// Mitsubishi GX Works2 project: ChangeMapping_Q   PLC: Q03UDV

TYPE SERVO_OBJECT : STRUCT
  wIndex : INT;  (* Index *)
  wSubIndex : INT;  (* Subindex *)
  dData : DINT;  (* Data *)
  wSize : INT;  (* Object size *)
END_STRUCT END_TYPE

TYPE EXTERNAL_DEVICE : STRUCT
  wIPaddress : ARRAY [0..1] OF INT;  (* IP address of external device *)
  wPortNo : INT;  (* Destination port number *)
  wResendNum : INT;  (* Number of resends *)
  wMonitoringTime : INT;  (* Arrival monitoring time *)
END_STRUCT END_TYPE

FUNCTION_BLOCK SVFB_WriteObject  // [00A] Object writing
VAR_INPUT
  i_bEN : BOOL;  (* Execution command *)
  i_stExtDevice : EXTERNAL_DEVICE;  (* External device *)
  i_stObjectInfo : SERVO_OBJECT;  (* Object information *)
END_VAR
VAR_OUTPUT
  o_bOK : BOOL;  (* Normal completion *)
  o_bErr : BOOL;  (* Error completion *)
  o_uErrID : WORD;  (* Error code *)
END_VAR
VAR
  w20CtrlData : ARRAY [0..19] OF INT;  (* SLMP Control data *)
  w10ReqData : ARRAY [0..9] OF INT;  (* SLMP Request frame *)
  w10ResData : ARRAY [0..9] OF INT;  (* SLMP Response frame *)
  b2ExecFlag : ARRAY [0..1] OF BOOL;  (* SLMP Completion device *)
END_VAR
VAR_OUTPUT
  o_bENO : BOOL;  (* Execution status *)
END_VAR
VAR
  wIPaddr12 : INT;  (* IP address *)
  wIPaddr34 : INT;  (* IP address *)
  wPortNo : INT;  (* Port number *)
  sDummy : STRING[32];  (* Dummy *)
  bBusy : BOOL;  (* Executing *)
  wResend : INT;  (* Number of resends *)
  wMonTime : INT;  (* Arrival monitoring time *)
  wIndex : INT;  (* Object index *)
  wSubIndex : INT;  (* Object sub index *)
  wSize : INT;  (* Object data size *)
  udData : DWORD;  (* Object data *)
  wDataL : INT;  (* data *)
  wDataH : INT;  (* data *)
  bInitialize : BOOL;  (* Initialization flag *)
END_VAR
(**************************************************************************
*
*    <FB NAME>    	SVFB_WriteObject
*    <Description>  	サーボアンプのオブジェクトデータを指定値に変更します。
*							Change the object data of the servo amplifier to the specified value.
*
*    COPYRIGHT (C) 2016 MITSUBISHI ELECTRIC CORPORATION ALL RIGHT RESERVED
**************************************************************************)

IF i_bEN THEN
	IF NOT(bInitialize) THEN
		bInitialize := TRUE;
		o_bENO	:= TRUE;
		o_uErrID	:= 0;

		(*--------------------------------------------------------------*
		|	入力ラベル取込み / Input label acquisition
		*---------------------------------------------------------------*)
		wIPaddr12	:= i_stExtDevice.wIPaddress[0];
		wIPaddr34	:= i_stExtDevice.wIPaddress[1];
		wPortNo		:= i_stExtDevice.wPortNo;
		wResend 	:= i_stExtDevice.wResendNum;
		wMonTime	:= i_stExtDevice.wMonitoringTime;
		wIndex		:= i_stObjectInfo.wIndex;
		wSubIndex	:= i_stObjectInfo.wSubIndex;
		wSize			:= i_stObjectInfo.wSize;
		udData		:= DINT_TO_DWORD(i_stObjectInfo.dData);
		wDataL		:= DWORD_TO_INT(udData);
		wDataH		:= DWORD_TO_INT(SHR(udData, 16));

		(* 入力ラベル範囲チェック / Input label range check *)
		MOV(((wResend < 0) OR (wResend > 15)), 3, wResend);
		MOV((wMonTime < 0), 0, wMonTime);
		MOV(((wSize < 1) OR (wSize > 4)), H100, o_uErrID);			(* エラーコード出力 / Error code output *)

		(*--------------------------------------------------------------*
		|	コントロールデータ / Control data
		*---------------------------------------------------------------*)
(*		FMOV(TRUE, K0, K20, w20CtrlData[0]);	*)		(* クリア / Clear *)
		w20CtrlData[0]  := H8081;				(* 実行・異常時完了タイプ / Execution/error completion type *)
		w20CtrlData[1]  := H0000;				(* 完了ステータス / Completion status *)
		w20CtrlData[2]  := H0002;				(* 自局使用チャンネル / Own station channel *)
		w20CtrlData[3]  := wIPaddr34;		(* 相手機器IPアドレス(第3，4オクテット) / IP address of external device (third and fourth octets) *)
		w20CtrlData[4]  := wIPaddr12;		(* 相手機器IPアドレス(第1，2オクテット) / IP address of external device (first and second octets) *)
		w20CtrlData[5]  := wPortNo;			(* 相手機器ポート番号 / Destination port number *)
		w20CtrlData[6]  := H0000;				(* 要求先ネットワーク番号 / Request destination network number *)
		w20CtrlData[7]  := H00FF;				(* 要求先局番 / Request destination station number *)
		w20CtrlData[8]  := H03FF;				(* 要求先ユニットI/O番号 / Request destination module I/O number *)
		w20CtrlData[9]  := H0000;				(* 要求先マルチドロップ局番 / Request destination multidrop station number *)
		w20CtrlData[10] := wResend;			(* 再送回数 / Number of resends *)
		w20CtrlData[11] := wMonTime;		(* 到達監視時間 / Arrival monitoring time *)
		w20CtrlData[12] := H0000;				(* 時計セットフラグ / Clock setting flag *)
		w20CtrlData[13] := H0000;				(* 時計データ(月・年下2桁)  / Clock data(Month, Year) *)
		w20CtrlData[14] := H0000;				(* 時計データ(時・日) / Clock data(Hour, Day) *)
		w20CtrlData[15] := H0000;				(* 時計データ(秒・分) / Clock data(Second, Minute) *)
		w20CtrlData[16] := H0000;				(* 時計データ(年上2桁・曜日)/ Clock data(Year, Day of the week) *)
		w20CtrlData[17] := H0000;				(* 異常検出機器IPアドレス(第3，4オクテット) / IP address of error detected device *)
		w20CtrlData[18] := H0000;				(* 異常検出機器IPアドレス(第1，2オクテット) / IP address of error detected device *)

		(*--------------------------------------------------------------*
		|	要求フレーム / Request frame
		*---------------------------------------------------------------*)
(*		FMOV(TRUE, K0, K10, w10ReqData[0]);	*)		(* クリア / Clear *)
		w10ReqData[0] := 12 + wSize;							(* 要求データ長 / Request data length *)
		w10ReqData[1] := K10;									(* 監視タイマ / Monitoring timer *)
		w10ReqData[2] := H4020;								(* コマンド / Command *)
		w10ReqData[3] := H2;									(* サブコマンド / Sub command *)
		w10ReqData[4] := wIndex;								(* インデックス / Index *)
		w10ReqData[5] := wSubIndex;							(* サブインデックス / Sub index *)
		w10ReqData[6] := wSize;								(* データサイズ / Number of data value *)
		w10ReqData[7] := wDataL;								(* データ(L) / Data(L) *)
		w10ReqData[8] := wDataH;								(* データ(H) / Data(H) *)

		(*--------------------------------------------------------------*
		|	応答フレーム / Response frame
		*---------------------------------------------------------------*)
		FMOV(TRUE, K0, K10, w10ResData[0]);			(* クリア / Clear *)

		(*--------------------------------------------------------------*
		|	命令完了の状態 / Completion status
		*---------------------------------------------------------------*)
		b2ExecFlag[0] := FALSE;				(* 完了デバイス / Completion device *)
		b2ExecFlag[1] := FALSE;				(* 完了時の状態表示デバイス / Completion status indication device *)

		IF (o_uErrID = 0) THEN
			bBusy := TRUE;
		ELSE
			o_bErr := TRUE;						(* エラー出力 / Error output *)
		END_IF;
	END_IF;

	(*--------------------------------------------------------------*
	|	要求送信 / Send request frame
	*---------------------------------------------------------------*)
	SP_SLMPSND(bBusy, sDummy, w20CtrlData[0], w10ReqData[0], w10ResData[0], b2ExecFlag);

	(*--------------------------------------------------------------*
	|	応答待ち / Waiting to receive response frame
	*---------------------------------------------------------------*)
	IF (bBusy) THEN
		IF b2ExecFlag[0] THEN			(* 命令完了 / Command Completion *)
			IF b2ExecFlag[1] THEN		(* 異常完了 / Abnormal completion *)
				o_bErr	:= TRUE;			(* エラー出力 / Error output *)
				o_uErrID	:= H200;			(* エラーコード出力 / Error code output *)
			ELSE
				IF (w10ResData[1] = 0) THEN
					o_bOK := TRUE;		(* 正常完了 / Normal completion *)
				ELSE
					o_bErr	:= TRUE;		(* エラー出力 / Error output *)
					o_uErrID	:= H200;		(* エラーコード出力 / Error code output *)
				END_IF;
			END_IF;
			bBusy := FALSE;
		END_IF;
	END_IF;

ELSE
	bInitialize	:= FALSE;
	bBusy		:= FALSE;
	o_bENO		:= FALSE;
	o_bOK		:= FALSE;
	o_bErr		:= FALSE;
	o_uErrID		:= 0;
END_IF;
END_FUNCTION_BLOCK

PROGRAM ServoObjectRW
VAR
  ExecuteRead : BOOL;  (* Execution command *)
  ExtDevice : EXTERNAL_DEVICE;  (* External device *)
  ObjectInfo : SERVO_OBJECT;  (* Object information *)
  ReadErrorID : WORD;  (* Error code *)
  WriteErrorID : WORD;  (* Error code *)
  ReadOK : BOOL;  (* Normal completion *)
  ReadError : BOOL;  (* Error completion *)
  WriteOK : BOOL;  (* Normal completion *)
  WriteError : BOOL;  (* Error completion *)
  SVFB_WriteObject_1 : SVFB_WriteObject;  (* Function block *)
  SVFB_ReadObject_1 : SVFB_ReadObject;  (* Function block *)
  ReadData : DINT;  (* Read data *)
  ExecuteWrite : BOOL;  (* Execution command *)
END_VAR
(* structured ladder/FBD written out as ST: instructions are called as NAME(EN, inputs, outputs); _pN, _eN, _tN stand for wires *)
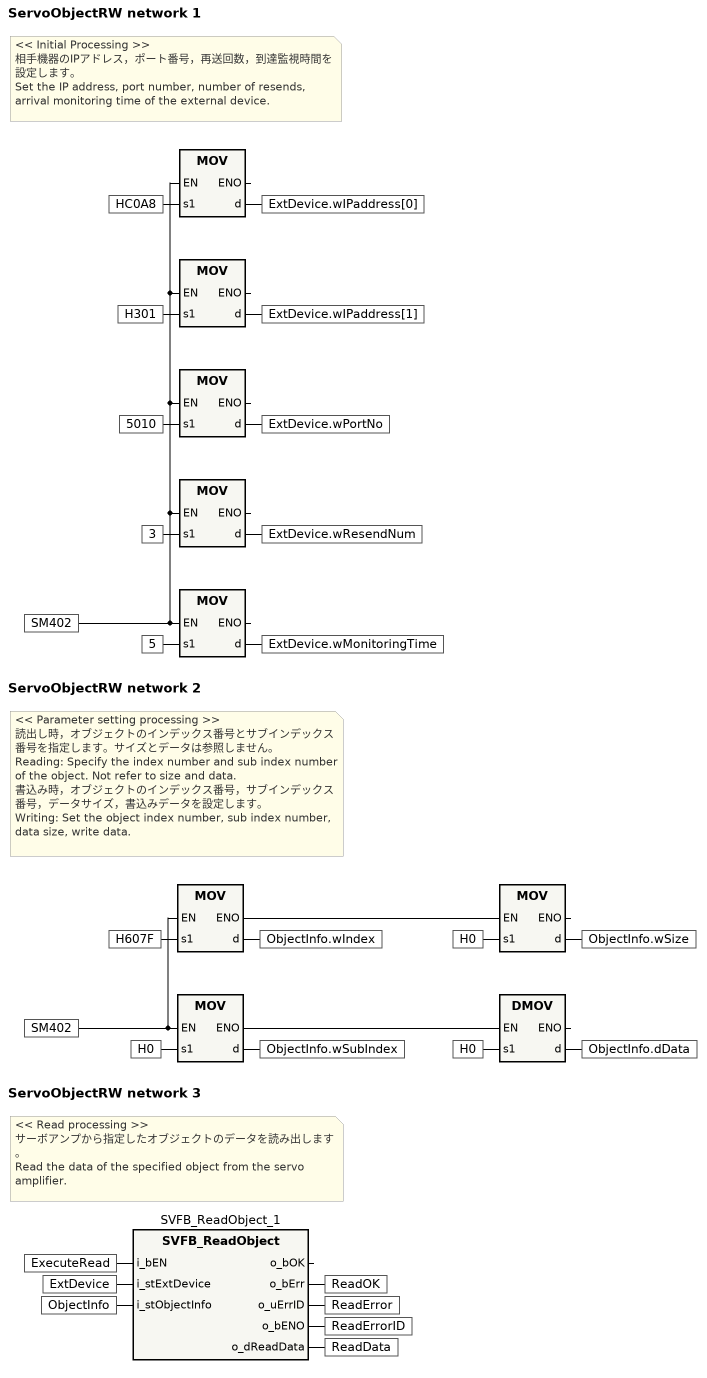
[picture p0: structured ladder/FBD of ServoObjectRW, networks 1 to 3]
(* network 1 *)
(* << Initial Processing >> /  / 相手機器のIPアドレス，ポート番号，再送回数，到達監視時間を設定します。 / Set the IP address, port number, number of resends, arrival monitoring time of the external device. *)
MOV(SM402, HC0A8, ExtDevice.wIPaddress[0]);
MOV(SM402, H301, ExtDevice.wIPaddress[1]);
MOV(SM402, 5010, ExtDevice.wPortNo);
MOV(SM402, 3, ExtDevice.wResendNum);
MOV(SM402, 5, ExtDevice.wMonitoringTime);
(* network 2 *)
(* << Parameter setting processing >> /  / 読出し時，オブジェクトのインデックス番号とサブインデックス番号を指定します。サイズとデータは参照しません。 / Reading: Specify the index number and sub index number of the object. Not refer to size and data. /  / 書込み時，オブジェクトのインデックス番号，サブインデックス番号，データサイズ，書込みデータを設定します。 / Writing: Set the object index number, sub index number, data size, write data. *)
_e1 := MOV(SM402, H607F, ObjectInfo.wIndex);
MOV(_e1, H0, ObjectInfo.wSize);
_e2 := MOV(SM402, H0, ObjectInfo.wSubIndex);
DMOV(_e2, H0, ObjectInfo.dData);
(* network 3 *)
(* << Read processing >> /  / サーボアンプから指定したオブジェクトのデータを読み出します。 / Read the data of the specified object from the servo amplifier. *)
SVFB_ReadObject_1(i_bEN := ExecuteRead, i_stExtDevice := ExtDevice, i_stObjectInfo := ObjectInfo, o_bErr => ReadOK, o_uErrID => ReadError, o_bENO => ReadErrorID, o_dReadData => ReadData);
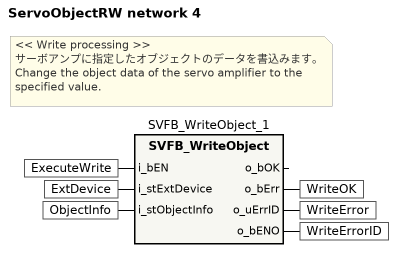
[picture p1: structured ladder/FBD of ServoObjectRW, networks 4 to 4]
(* network 4 *)
(* << Write processing >> /  / サーボアンプに指定したオブジェクトのデータを書込みます。 / Change the object data of the servo amplifier to the specified value. *)
SVFB_WriteObject_1(i_bEN := ExecuteWrite, i_stExtDevice := ExtDevice, i_stObjectInfo := ObjectInfo, o_bErr => WriteOK, o_uErrID => WriteError, o_bENO => WriteErrorID);
END_PROGRAM

FUNCTION_BLOCK SVFB_ReadObject  // [00A] Object reading
VAR_INPUT
  i_bEN : BOOL;  (* Execution command *)
  i_stExtDevice : EXTERNAL_DEVICE;  (* External device *)
  i_stObjectInfo : SERVO_OBJECT;  (* Object information *)
END_VAR
VAR_OUTPUT
  o_bOK : BOOL;  (* Normal completion *)
  o_bErr : BOOL;  (* Error completion *)
  o_uErrID : WORD;  (* Error code *)
END_VAR
VAR
  w20CtrlData : ARRAY [0..19] OF INT;  (* SLMP Control data *)
  w10ReqData : ARRAY [0..9] OF INT;  (* SLMP Request frame *)
  w10ResData : ARRAY [0..9] OF INT;  (* SLMP Response frame *)
  b2ExecFlag : ARRAY [0..1] OF BOOL;  (* SLMP Completion device *)
END_VAR
VAR_OUTPUT
  o_bENO : BOOL;  (* Execution status *)
END_VAR
VAR
  wIndex : INT;  (* Object index *)
  wSubIndex : INT;  (* Object sub index *)
  sDummy : STRING[32];  (* Dummy *)
  wReadData : INT;  (* Read data *)
  dReadData : DINT;  (* Read data *)
END_VAR
VAR_OUTPUT
  o_dReadData : DINT;  (* Read data *)
END_VAR
VAR
  udReadData : DWORD;  (* Read data *)
  bBusy : BOOL;  (* Executing *)
  wIPaddr12 : INT;  (* IP address *)
  wIPaddr34 : INT;  (* IP address *)
  wPortNo : INT;  (* Port number *)
  wResend : INT;  (* Number of resends *)
  wMonTime : INT;  (* Arrival monitoring time *)
  bInitialize : BOOL;  (* Initialization flag *)
END_VAR
(**************************************************************************
*
*    <FB NAME>		SVFB_ReadObject
*    <Description>		サーボアンプから指定オブジェクトのデータを読み出します。
*							Read the data of the specified object from the servo amplifier.
*
*    COPYRIGHT (C) 2016 MITSUBISHI ELECTRIC CORPORATION ALL RIGHT RESERVED
**************************************************************************)

IF i_bEN THEN
	IF NOT(bInitialize) THEN
		bInitialize	:= TRUE;
		o_bENO	:= TRUE;
		o_uErrID	:= 0;
		o_dReadData := 0;
		dReadData := 0;

		(*--------------------------------------------------------------*
		|	入力ラベル取込み / Input label acquisition
		*---------------------------------------------------------------*)
		wIPaddr12	:= i_stExtDevice.wIPaddress[0];
		wIPaddr34	:= i_stExtDevice.wIPaddress[1];
		wPortNo		:= i_stExtDevice.wPortNo;
		wResend 	:= i_stExtDevice.wResendNum;
		wMonTime	:= i_stExtDevice.wMonitoringTime;
		wIndex		:= i_stObjectInfo.wIndex;
		wSubIndex	:= i_stObjectInfo.wSubIndex;

		(* 入力ラベル範囲チェック / Input label range check *)
		MOV(((wResend < 0) OR (wResend > 15)), 3, wResend);
		MOV((wMonTime < 0), 0, wMonTime);

		(*--------------------------------------------------------------*
		|	コントロールデータ / Control data
		*---------------------------------------------------------------*)
(*		FMOV(TRUE, K0, K20, w20CtrlData[0]);	*)		(* クリア / Clear *)
		w20CtrlData[0]  := H8081;				(* 実行・異常時完了タイプ / Execution/error completion type *)
		w20CtrlData[1]  := H0000;				(* 完了ステータス / Completion status *)
		w20CtrlData[2]  := H0002;				(* 自局使用チャンネル / Own station channel *)
		w20CtrlData[3]  := wIPaddr34;		(* 相手機器IPアドレス(第3，4オクテット) / IP address of external device (third and fourth octets) *)
		w20CtrlData[4]  := wIPaddr12;		(* 相手機器IPアドレス(第1，2オクテット) / IP address of external device (first and second octets) *)
		w20CtrlData[5]  := wPortNo;			(* 相手機器ポート番号 / Destination port number *)
		w20CtrlData[6]  := H0000;				(* 要求先ネットワーク番号 / Request destination network number *)
		w20CtrlData[7]  := H00FF;				(* 要求先局番 / Request destination station number *)
		w20CtrlData[8]  := H03FF;				(* 要求先ユニットI/O番号 / Request destination module I/O number *)
		w20CtrlData[9]  := H0000;				(* 要求先マルチドロップ局番 / Request destination multidrop station number *)
		w20CtrlData[10] := wResend;			(* 再送回数 / Number of resends *)
		w20CtrlData[11] := wMonTime;		(* 到達監視時間 / Arrival monitoring time *)
		w20CtrlData[12] := H0000;				(* 時計セットフラグ / Clock setting flag *)
		w20CtrlData[13] := H0000;				(* 時計データ(月・年下2桁)  / Clock data(Month, Year) *)
		w20CtrlData[14] := H0000;				(* 時計データ(時・日) / Clock data(Hour, Day) *)
		w20CtrlData[15] := H0000;				(* 時計データ(秒・分) / Clock data(Second, Minute) *)
		w20CtrlData[16] := H0000;				(* 時計データ(年上2桁・曜日)/ Clock data(Year, Day of the week) *)
		w20CtrlData[17] := H0000;				(* 異常検出機器IPアドレス(第3，4オクテット) / IP address of error detected device *)
		w20CtrlData[18] := H0000;				(* 異常検出機器IPアドレス(第1，2オクテット) / IP address of error detected device *)

		(*--------------------------------------------------------------*
		|	要求フレーム / Request frame
		*---------------------------------------------------------------*)
(*		FMOV(TRUE, K0, K10, w10ReqData[0]);	*)		(* クリア / Clear *)
		w10ReqData[0] := 12;									(* 要求データ長 / Request data length *)
		w10ReqData[1] := K10;									(* 監視タイマ / Monitoring timer *)
		w10ReqData[2] := H4020;								(* コマンド / Command *)
		w10ReqData[3] := H1;									(* サブコマンド / Sub command *)
		w10ReqData[4] := wIndex;								(* インデックス / Index *)
		w10ReqData[5] := wSubIndex;							(* サブインデックス / Sub index *)
		w10ReqData[6] := 0;										(* データサイズ / Number of data value *)

		(*--------------------------------------------------------------*
		|	応答フレーム / Response frame
		*---------------------------------------------------------------*)
		FMOV(TRUE, K0, K10, w10ResData[0]);			(* クリア / Clear *)

		(*--------------------------------------------------------------*
		|	命令完了の状態 / Completion status
		*---------------------------------------------------------------*)
		b2ExecFlag[0] := FALSE;				(* 完了デバイス / Completion device *)
		b2ExecFlag[1] := FALSE;				(* 完了時の状態表示デバイス / Completion status indication device *)

		bBusy := TRUE;
	END_IF;

	(*--------------------------------------------------------------*
	|	要求送信 / Send request frame
	*---------------------------------------------------------------*)
	SP_SLMPSND(bBusy, sDummy, w20CtrlData[0], w10ReqData[0], w10ResData[0], b2ExecFlag);

	(*--------------------------------------------------------------*
	|	応答待ち / Waiting to receive response frame
	*---------------------------------------------------------------*)
	IF (bBusy) THEN
		IF b2ExecFlag[0] THEN			(* 命令完了 / Command Completion *)
			IF b2ExecFlag[1] THEN		(* 異常完了 / Abnormal completion *)
				o_bErr	:= TRUE;			(* エラー出力 / Error output *)
				o_uErrID	:= H200;			(* エラーコード出力 / Error code output *)
			ELSE								(* 正常完了 / Normal completion *)
				IF (w10ResData[1] = 0) THEN
					IF (w10ResData[4] <= 2) THEN
						MOV(TRUE, w10ResData[5], wReadData);
						dReadData := INT_TO_DINT(wReadData);
					ELSE
						udReadData := SHL(INT_TO_DWORD(w10ResData[6]), 16);
						udReadData := udReadData OR (INT_TO_DWORD(w10ResData[5]));
						dReadData := DWORD_TO_DINT(udReadData);
					END_IF;
					o_bOK := TRUE;
					o_dReadData := dReadData;
				ELSE
					o_bErr	:= TRUE;		(* エラー出力 / Error output *)
					o_uErrID	:= H200;		(* エラーコード出力 / Error code output *)
				END_IF;
			END_IF;
			bBusy := FALSE;
		END_IF;
	END_IF;

ELSE
	bInitialize	:= FALSE;
	bBusy		:= FALSE;
	o_bENO		:= FALSE;
	o_bOK		:= FALSE;
	o_bErr		:= FALSE;
	o_uErrID		:= 0;
END_IF;
END_FUNCTION_BLOCK

FUNCTION_BLOCK SVFB_WriteMultiObject  // [00A] Writing multiple objects
VAR_INPUT
  i_stExtDevice : EXTERNAL_DEVICE;  (* External device *)
  i_stObjectTbl : ARRAY [0..33] OF SERVO_OBJECT;  (* Object table *)
  i_wNum : INT;  (* Number registered *)
  i_bEN : BOOL;  (* Execution command *)
END_VAR
VAR_OUTPUT
  o_bENO : BOOL;  (* Execution status *)
  o_bOK : BOOL;  (* Normal completion *)
  o_bBusy : BOOL;  (* Executing *)
  o_bErr : BOOL;  (* Error completion *)
  o_uErrID : WORD;  (* Error code *)
END_VAR
VAR
  bFbEn : BOOL;  (* FB execution command *)
  bFbEno : BOOL;  (* FB execution status *)
  bFbOk : BOOL;  (* FB normal completion *)
  bFbErr : BOOL;  (* FB error completion *)
  uFbErrID : WORD;  (* FB error code *)
  wInstructSQ : INT;  (* Sequence number *)
  wNum : INT;  (* Number registered *)
  SVFB_WriteObject_1 : SVFB_WriteObject;  (* Function block *)
  wWaitCount : INT;
  bInitialize : BOOL;  (* Initialization flag *)
  wIndex : INT;  (* Index *)
END_VAR
(**************************************************************************
*
*    <FB NAME>    	SVFB_WriteMultiObject
*    <Description>  	サーボアンプの複数のオブジェクトデータを変更します。
*							Changes multiple object data of the servo amplifier.
*
*    COPYRIGHT (C) 2016 MITSUBISHI ELECTRIC CORPORATION ALL RIGHT RESERVED
**************************************************************************)

IF i_bEN THEN
	IF NOT(bInitialize) THEN
		bInitialize := TRUE;
		o_bENO	:= TRUE;
		o_uErrID	:= 0;

		wIndex	:= 0;
		wWaitCount := 0;

		(* 入力ラベル範囲チェック / Input label range check *)
		wNum := i_wNum;
		IF ((wNum < 1) OR (wNum > 34)) THEN
			o_uErrID := H101;
			wInstructSQ := 3;
		ELSE
			o_bBusy := TRUE;
			bFbEn	:= TRUE;
			wInstructSQ := 1;
		END_IF;
	END_IF;

	(*--------------------------------------------------------------*
	|	オブジェクトデータ書込み / Writing object data
	*---------------------------------------------------------------*)
	SVFB_WriteObject_1(i_bEN := bFbEn, i_stExtDevice := i_stExtDevice, i_stObjectInfo := i_stObjectTbl[wIndex],
								o_bENO := bFbEno, o_bOK := bFbOk, o_bErr := bFbErr, o_uErrID := uFbErrID);

	IF (wInstructSQ = 1) THEN		(* ファンクションブロック完了待ち / Wait for completion of function block *)
		IF bFbOk THEN
			wInstructSQ := 2;
		ELSIF bFbErr THEN
			o_uErrID := uFbErrID;
			wInstructSQ := 2;
		ELSE
			;
		END_IF;
	ELSIF (wInstructSQ = 2) THEN	(* 命令リセットと次データセット / Instruction reset and next data set *)
		IF bFbEn THEN
			bFbEn := FALSE;
		ELSE
			IF (o_uErrID = 0) THEN
				wWaitCount := wWaitCount + 1;
				IF (wWaitCount > 2) THEN
					wWaitCount := 0;
					wIndex := wIndex + 1;
					IF (wIndex >= wNum) THEN
						wInstructSQ := 3;
					ELSE
						bFbEn	:= TRUE;
						wInstructSQ := 1;
					END_IF;
				END_IF;
			ELSE
				wInstructSQ := 3;
			END_IF;
		END_IF;
	ELSE										(* 終了処理 / End processing *)
		IF (o_uErrID = 0) THEN
			o_bOK	:= TRUE;
			o_bErr	:= FALSE;
		ELSE
			o_bOK	:= FALSE;
			o_bErr	:= TRUE;
		END_IF;
		o_bBusy	:= FALSE;
	END_IF;

ELSE
	bInitialize := FALSE;
	wInstructSQ := 0;
	wIndex	:= 0;
	bFbEn	:= FALSE;
	bFbEno	:= FALSE;
	bFbOk	:= FALSE;
	bFbErr	:= FALSE;
	uFbErrID := 0;

	o_bENO	:= FALSE;
	o_bOK	:= FALSE;
	o_bBusy	:= FALSE;
	o_bErr	:= FALSE;
	o_uErrID	:= 0;
END_IF;
END_FUNCTION_BLOCK

PROGRAM ChangeMap
VAR
  AmpInfo : EXTERNAL_DEVICE;  (* External device *)
  MapTable : ARRAY [0..33] OF SERVO_OBJECT;  (* Object information *)
  StartChangeMap : BOOL;  (* Execution command *)
  Done : BOOL;  (* Normal completion *)
  Error : BOOL;  (* Error completion *)
  ErrorID : WORD;  (* Error code *)
  SVFB_WriteMultiObject_1 : SVFB_WriteMultiObject;  (* Function block *)
END_VAR
(* structured ladder/FBD written out as ST: instructions are called as NAME(EN, inputs, outputs); _pN, _eN, _tN stand for wires *)
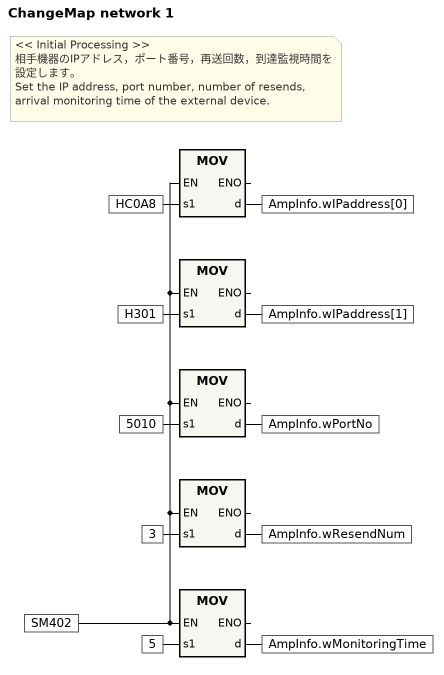
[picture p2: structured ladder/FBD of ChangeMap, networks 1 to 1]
(* network 1 *)
(* << Initial Processing >> /  / 相手機器のIPアドレス，ポート番号，再送回数，到達監視時間を設定します。 / Set the IP address, port number, number of resends, arrival monitoring time of the external device. *)
MOV(SM402, HC0A8, AmpInfo.wIPaddress[0]);
MOV(SM402, H301, AmpInfo.wIPaddress[1]);
MOV(SM402, 5010, AmpInfo.wPortNo);
MOV(SM402, 3, AmpInfo.wResendNum);
MOV(SM402, 5, AmpInfo.wMonitoringTime);
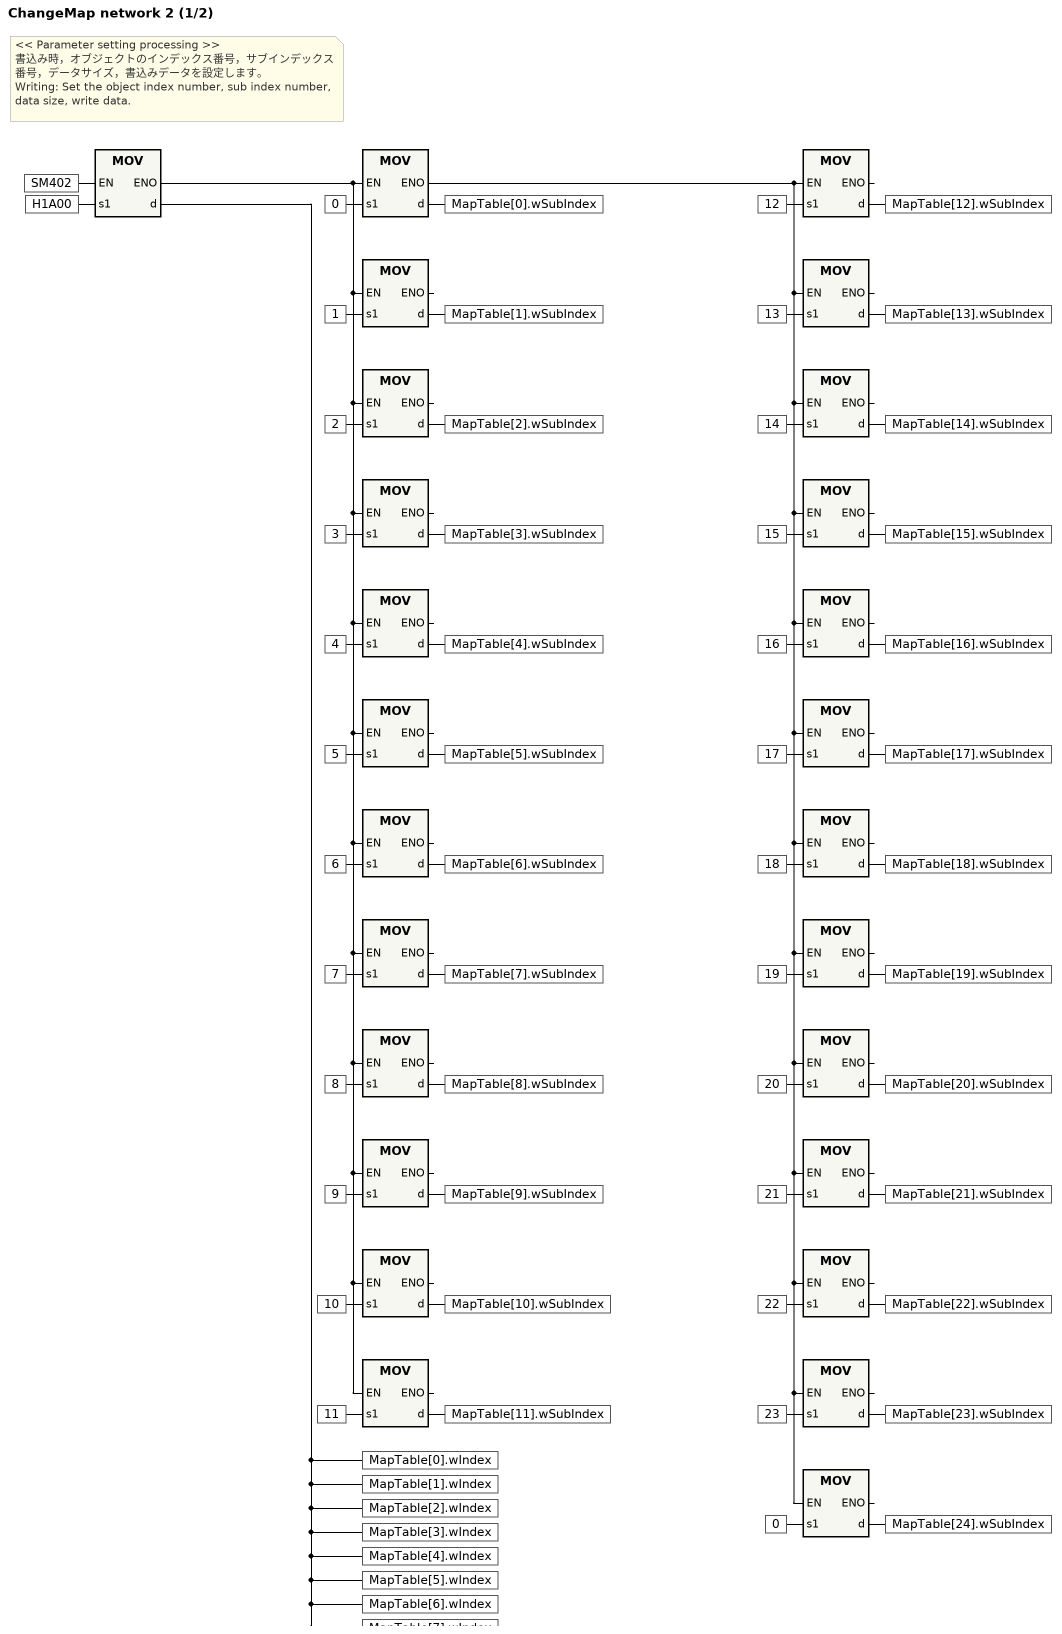
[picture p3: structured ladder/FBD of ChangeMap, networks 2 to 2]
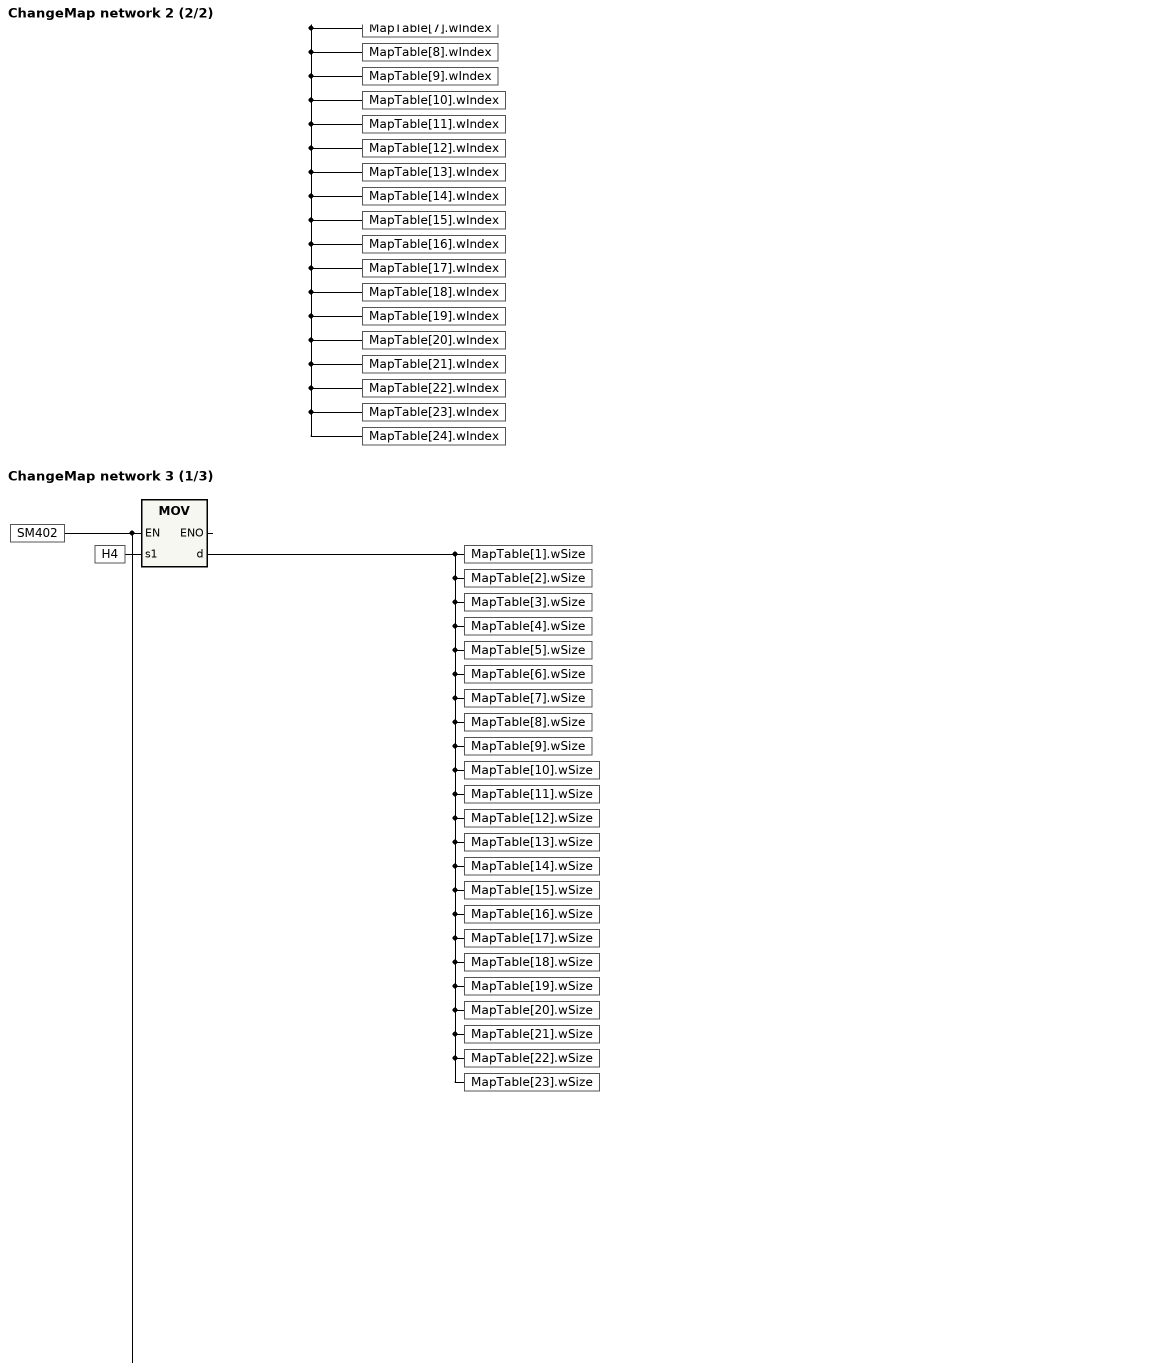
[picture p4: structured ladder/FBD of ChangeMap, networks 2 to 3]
(* network 2 *)
(* << Parameter setting processing >> /  / 書込み時，オブジェクトのインデックス番号，サブインデックス番号，データサイズ，書込みデータを設定します。 / Writing: Set the object index number, sub index number, data size, write data. *)
_e1 := MOV(SM402, H1A00, MapTable[0].wIndex);
_e2 := MOV(_e1, 0, MapTable[0].wSubIndex);
MOV(_e2, 12, MapTable[12].wSubIndex);
MapTable[1].wIndex := MapTable[0].wIndex;
MapTable[2].wIndex := MapTable[0].wIndex;
MapTable[3].wIndex := MapTable[0].wIndex;
MOV(_e1, 1, MapTable[1].wSubIndex);
MOV(_e2, 13, MapTable[13].wSubIndex);
MapTable[4].wIndex := MapTable[0].wIndex;
MapTable[5].wIndex := MapTable[0].wIndex;
MapTable[6].wIndex := MapTable[0].wIndex;
MapTable[7].wIndex := MapTable[0].wIndex;
MOV(_e1, 2, MapTable[2].wSubIndex);
MOV(_e2, 14, MapTable[14].wSubIndex);
MapTable[8].wIndex := MapTable[0].wIndex;
MapTable[9].wIndex := MapTable[0].wIndex;
MapTable[10].wIndex := MapTable[0].wIndex;
MapTable[11].wIndex := MapTable[0].wIndex;
MOV(_e1, 3, MapTable[3].wSubIndex);
MOV(_e2, 15, MapTable[15].wSubIndex);
MapTable[12].wIndex := MapTable[0].wIndex;
MapTable[13].wIndex := MapTable[0].wIndex;
MapTable[14].wIndex := MapTable[0].wIndex;
MapTable[15].wIndex := MapTable[0].wIndex;
MOV(_e1, 4, MapTable[4].wSubIndex);
MOV(_e2, 16, MapTable[16].wSubIndex);
MapTable[16].wIndex := MapTable[0].wIndex;
MapTable[17].wIndex := MapTable[0].wIndex;
MapTable[18].wIndex := MapTable[0].wIndex;
MapTable[19].wIndex := MapTable[0].wIndex;
MOV(_e1, 5, MapTable[5].wSubIndex);
MOV(_e2, 17, MapTable[17].wSubIndex);
MapTable[20].wIndex := MapTable[0].wIndex;
MapTable[21].wIndex := MapTable[0].wIndex;
MapTable[22].wIndex := MapTable[0].wIndex;
MapTable[23].wIndex := MapTable[0].wIndex;
MOV(_e1, 6, MapTable[6].wSubIndex);
MOV(_e2, 18, MapTable[18].wSubIndex);
MapTable[24].wIndex := MapTable[0].wIndex;
MOV(_e1, 7, MapTable[7].wSubIndex);
MOV(_e2, 19, MapTable[19].wSubIndex);
MOV(_e1, 8, MapTable[8].wSubIndex);
MOV(_e2, 20, MapTable[20].wSubIndex);
MOV(_e1, 9, MapTable[9].wSubIndex);
MOV(_e2, 21, MapTable[21].wSubIndex);
MOV(_e1, 10, MapTable[10].wSubIndex);
MOV(_e2, 22, MapTable[22].wSubIndex);
MOV(_e1, 11, MapTable[11].wSubIndex);
MOV(_e2, 23, MapTable[23].wSubIndex);
MOV(_e2, 0, MapTable[24].wSubIndex);
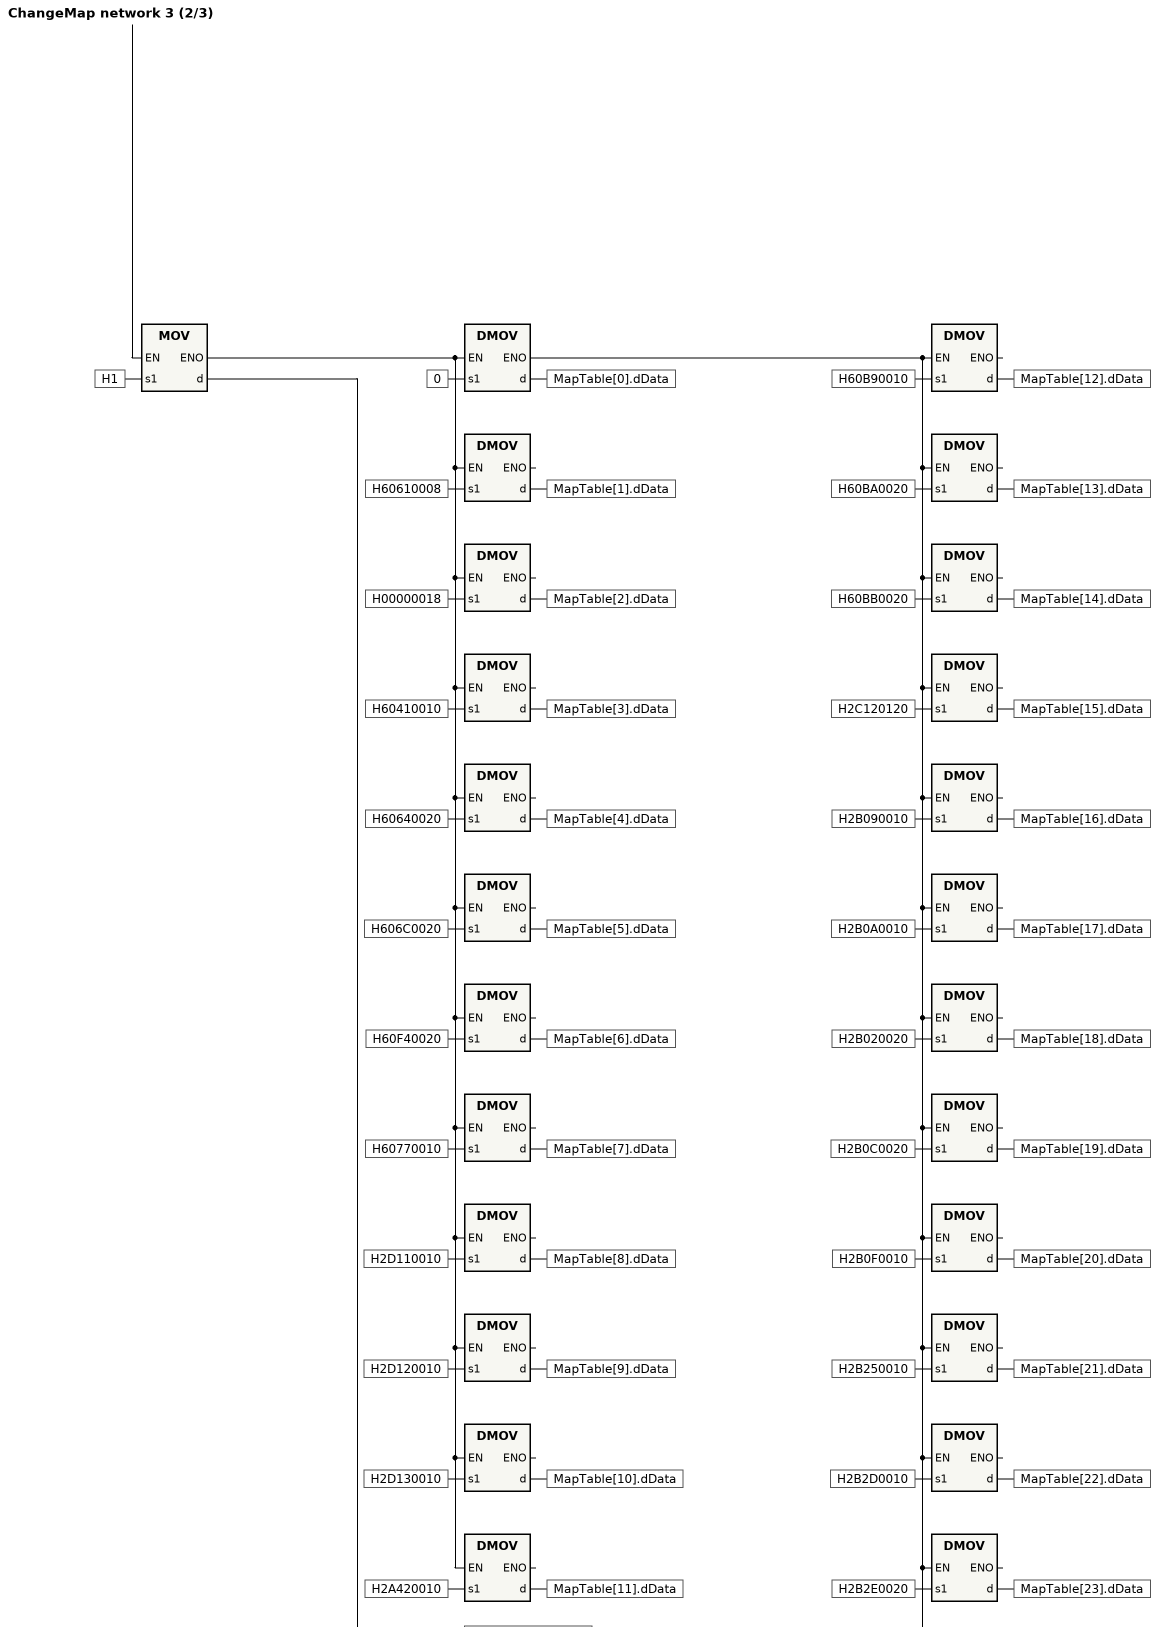
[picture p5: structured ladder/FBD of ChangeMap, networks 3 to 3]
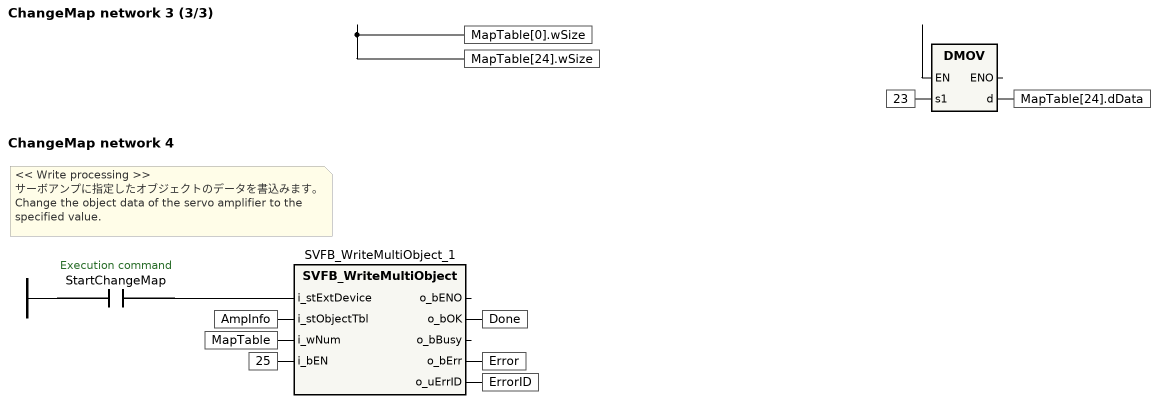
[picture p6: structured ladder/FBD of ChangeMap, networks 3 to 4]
(* network 3 *)
_e1 := MOV(SM402, H1, MapTable[0].wSize);
_e2 := DMOV(_e1, 0, MapTable[0].dData);
DMOV(_e2, H60B90010, MapTable[12].dData);
MapTable[24].wSize := MapTable[0].wSize;
DMOV(_e1, H60610008, MapTable[1].dData);
DMOV(_e2, H60BA0020, MapTable[13].dData);
MOV(SM402, H4, MapTable[1].wSize);
DMOV(_e1, H00000018, MapTable[2].dData);
DMOV(_e2, H60BB0020, MapTable[14].dData);
MapTable[2].wSize := MapTable[1].wSize;
MapTable[3].wSize := MapTable[1].wSize;
MapTable[4].wSize := MapTable[1].wSize;
MapTable[5].wSize := MapTable[1].wSize;
DMOV(_e1, H60410010, MapTable[3].dData);
DMOV(_e2, H2C120120, MapTable[15].dData);
MapTable[6].wSize := MapTable[1].wSize;
MapTable[7].wSize := MapTable[1].wSize;
MapTable[8].wSize := MapTable[1].wSize;
MapTable[9].wSize := MapTable[1].wSize;
DMOV(_e1, H60640020, MapTable[4].dData);
DMOV(_e2, H2B090010, MapTable[16].dData);
MapTable[10].wSize := MapTable[1].wSize;
MapTable[11].wSize := MapTable[1].wSize;
MapTable[12].wSize := MapTable[1].wSize;
MapTable[13].wSize := MapTable[1].wSize;
DMOV(_e1, H606C0020, MapTable[5].dData);
DMOV(_e2, H2B0A0010, MapTable[17].dData);
MapTable[14].wSize := MapTable[1].wSize;
MapTable[15].wSize := MapTable[1].wSize;
MapTable[16].wSize := MapTable[1].wSize;
MapTable[17].wSize := MapTable[1].wSize;
DMOV(_e1, H60F40020, MapTable[6].dData);
DMOV(_e2, H2B020020, MapTable[18].dData);
MapTable[18].wSize := MapTable[1].wSize;
MapTable[19].wSize := MapTable[1].wSize;
MapTable[20].wSize := MapTable[1].wSize;
MapTable[21].wSize := MapTable[1].wSize;
DMOV(_e1, H60770010, MapTable[7].dData);
DMOV(_e2, H2B0C0020, MapTable[19].dData);
MapTable[22].wSize := MapTable[1].wSize;
MapTable[23].wSize := MapTable[1].wSize;
DMOV(_e1, H2D110010, MapTable[8].dData);
DMOV(_e2, H2B0F0010, MapTable[20].dData);
DMOV(_e1, H2D120010, MapTable[9].dData);
DMOV(_e2, H2B250010, MapTable[21].dData);
DMOV(_e1, H2D130010, MapTable[10].dData);
DMOV(_e2, H2B2D0010, MapTable[22].dData);
DMOV(_e1, H2A420010, MapTable[11].dData);
DMOV(_e2, H2B2E0020, MapTable[23].dData);
DMOV(_e2, 23, MapTable[24].dData);
(* network 4 *)
(* << Write processing >> /  / サーボアンプに指定したオブジェクトのデータを書込みます。 / Change the object data of the servo amplifier to the specified value. *)
SVFB_WriteMultiObject_1(i_stExtDevice := StartChangeMap, i_stObjectTbl := AmpInfo, i_wNum := MapTable, i_bEN := 25, o_bOK => Done, o_bErr => Error, o_uErrID => ErrorID);
END_PROGRAM

FUNCTION_BLOCK SVFB_ReadMultiObject  // [00A] Reading multiple objects
VAR
  bFbEn : BOOL;  (* FB execution command *)
  bFbEno : BOOL;  (* FB execution status *)
  bFbOk : BOOL;  (* FB normal completion *)
  bFbErr : BOOL;  (* FB error completion *)
  uFbErrID : WORD;  (* FB error code *)
  wInstructSQ : INT;  (* Sequence number *)
END_VAR
VAR_INPUT
  i_bEN : BOOL;  (* Execution command *)
  i_stExtDevice : EXTERNAL_DEVICE;  (* External device *)
END_VAR
VAR_OUTPUT
  o_bENO : BOOL;  (* Execution status *)
  o_bOK : BOOL;  (* Normal completion *)
  o_bBusy : BOOL;  (* Executing *)
  o_bErr : BOOL;  (* Error completion *)
  o_uErrID : WORD;  (* Error code *)
END_VAR
VAR
  wIndex : INT;  (* Index *)
  dReadData : DINT;  (* Read data *)
  wNum : INT;  (* Number registered *)
END_VAR
VAR_INPUT
  i_wNum : INT;  (* Number registered *)
END_VAR
VAR
  SVFB_ReadObject_1 : SVFB_ReadObject;  (* Function block *)
END_VAR
VAR_IN_OUT
  io_stObjectTbl : ARRAY [0..33] OF SERVO_OBJECT;  (* Object table *)
END_VAR
VAR
  wWaitCount : INT;
  bInitialize : BOOL;  (* Initialization flag *)
END_VAR
(**************************************************************************
*
*    <FB NAME>    	SVFB_ReadMultiObject
*    <Description>  	サーボアンプから複数のオブジェクトデータを読み出します。
*							Read multiple object data from the servo amplifier.
*
*    COPYRIGHT (C) 2016 MITSUBISHI ELECTRIC CORPORATION ALL RIGHT RESERVED
**************************************************************************)

IF i_bEN THEN
	IF NOT(bInitialize) THEN
		bInitialize := TRUE;
		o_bENO	:= TRUE;
		o_uErrID	:= 0;

		wIndex	:= 0;
		dReadData	:= 0;
		wWaitCount := 0;

		(* 入力ラベル範囲チェック / Input label range check *)
		wNum := i_wNum;
		IF ((wNum < 1) OR (wNum > 34)) THEN
			o_uErrID := H101;
			wInstructSQ := 3;
		ELSE
			o_bBusy := TRUE;
			bFbEn	:= TRUE;
			wInstructSQ := 1;
		END_IF;
	END_IF;

	(*--------------------------------------------------------------*
	|	オブジェクトデータ読出し / Reading object data
	*---------------------------------------------------------------*)
	SVFB_ReadObject_1(i_bEN := bFbEn, i_stExtDevice := i_stExtDevice, i_stObjectInfo := io_stObjectTbl[wIndex],
								o_bENO := bFbEno, o_bOK := bFbOk, o_bErr := bFbErr, o_uErrID := uFbErrID, o_dReadData := dReadData);

	IF (wInstructSQ = 1) THEN		(* ファンクションブロック完了待ち / Wait for completion of function block *)
		IF bFbOk THEN
			io_stObjectTbl[wIndex].dData := dReadData;
			wInstructSQ := 2;
		ELSIF bFbErr THEN
			o_uErrID := uFbErrID;
			wInstructSQ := 2;
		ELSE
			;
		END_IF;
	ELSIF (wInstructSQ = 2) THEN	(* 命令リセットと次データセット / Instruction reset and next data set *)
		IF bFbEn THEN
			bFbEn := FALSE;
		ELSE
			IF (o_uErrID = 0) THEN
				wWaitCount := wWaitCount + 1;
				IF (wWaitCount > 2) THEN
					wWaitCount := 0;
					wIndex := wIndex + 1;
					IF (wIndex >= wNum) THEN
						wInstructSQ := 3;
					ELSE
						bFbEn	:= TRUE;
						dReadData := 0;
						wInstructSQ := 1;
					END_IF;
				END_IF;
			ELSE
				wInstructSQ := 3;
			END_IF;
		END_IF;
	ELSE										(* 終了処理 / End processing *)
		IF (o_uErrID = 0) THEN
			o_bOK	:= TRUE;
			o_bErr	:= FALSE;
		ELSE
			o_bOK	:= FALSE;
			o_bErr	:= TRUE;
		END_IF;
		o_bBusy	:= FALSE;
	END_IF;

ELSE
	bInitialize := FALSE;
	wInstructSQ := 0;
	wIndex	:= 0;
	bFbEn	:= FALSE;
	bFbEno	:= FALSE;
	bFbOk	:= FALSE;
	bFbErr	:= FALSE;
	uFbErrID := 0;

	o_bENO	:= FALSE;
	o_bOK	:= FALSE;
	o_bBusy	:= FALSE;
	o_bErr	:= FALSE;
	o_uErrID	:= 0;
END_IF;
END_FUNCTION_BLOCK

PROGRAM ReadMap
VAR
  AmpInfo : EXTERNAL_DEVICE;  (* External device *)
  MapTable : ARRAY [0..33] OF SERVO_OBJECT;  (* Object information *)
  Done : BOOL;  (* Normal completion *)
  Error : BOOL;  (* Error completion *)
  ErrorID : WORD;  (* Error code *)
  StartReadMap : BOOL;  (* Execution command *)
  SVFB_ReadMultiObject_1 : SVFB_ReadMultiObject;  (* Function block *)
END_VAR
(* structured ladder/FBD written out as ST: instructions are called as NAME(EN, inputs, outputs); _pN, _eN, _tN stand for wires *)
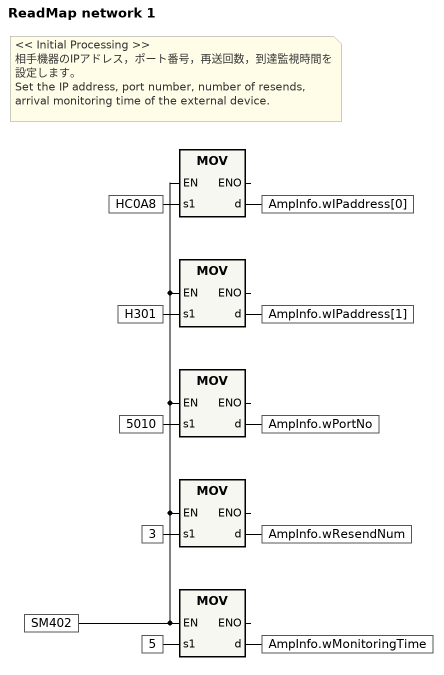
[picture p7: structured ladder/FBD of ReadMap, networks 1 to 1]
(* network 1 *)
(* << Initial Processing >> /  / 相手機器のIPアドレス，ポート番号，再送回数，到達監視時間を設定します。 / Set the IP address, port number, number of resends, arrival monitoring time of the external device. *)
MOV(SM402, HC0A8, AmpInfo.wIPaddress[0]);
MOV(SM402, H301, AmpInfo.wIPaddress[1]);
MOV(SM402, 5010, AmpInfo.wPortNo);
MOV(SM402, 3, AmpInfo.wResendNum);
MOV(SM402, 5, AmpInfo.wMonitoringTime);
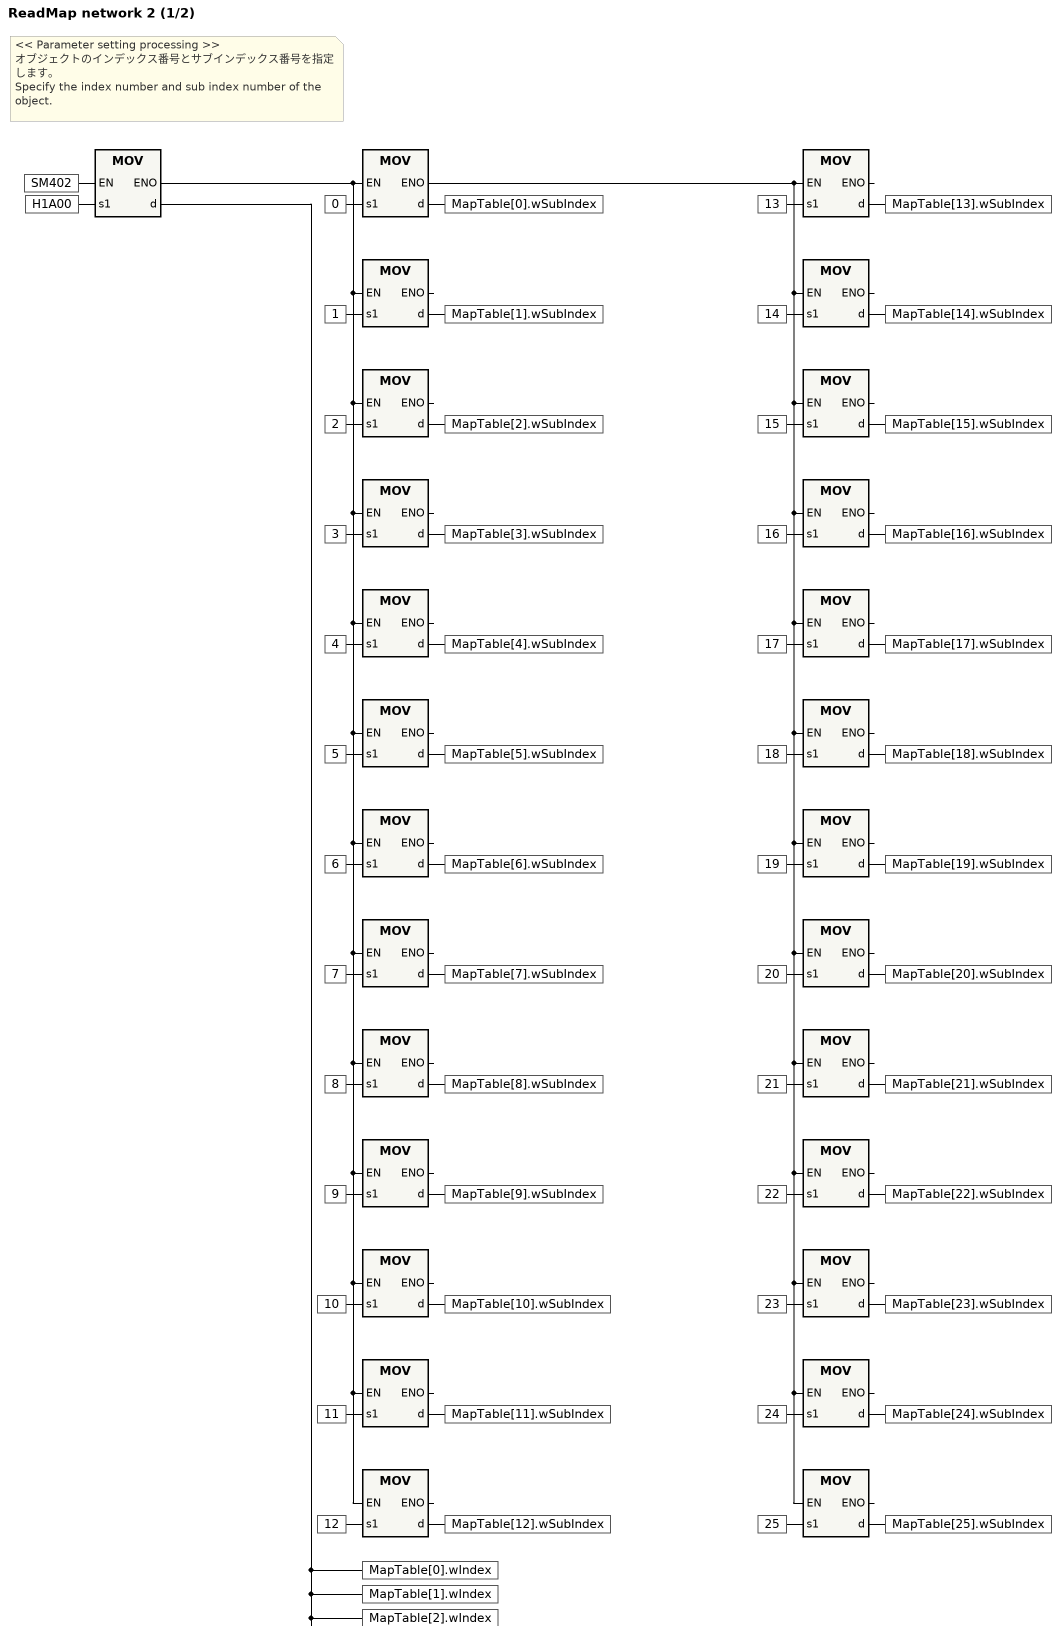
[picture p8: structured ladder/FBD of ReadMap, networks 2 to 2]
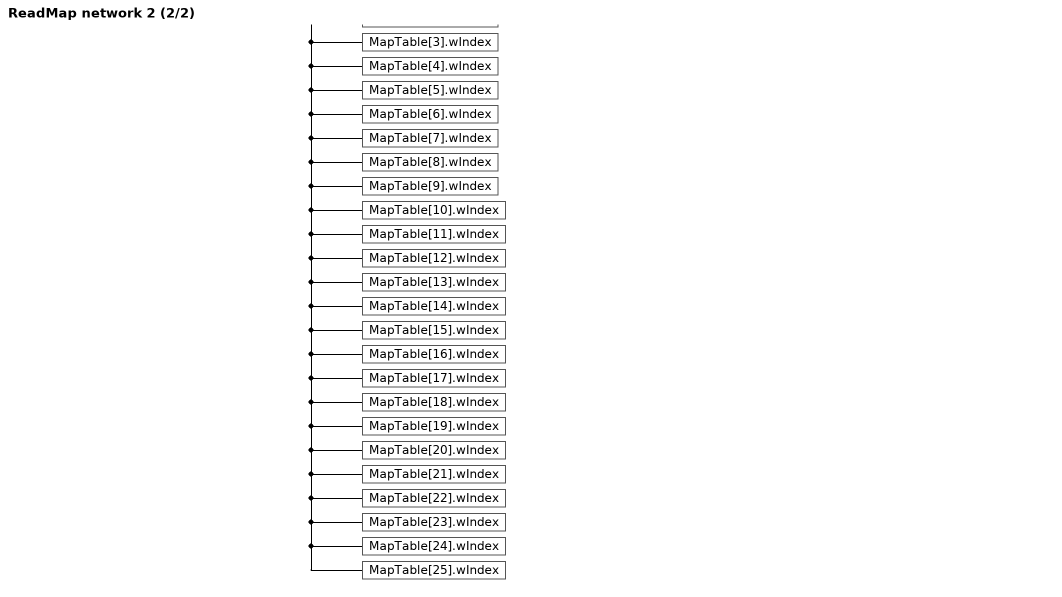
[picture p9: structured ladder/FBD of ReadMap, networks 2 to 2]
(* network 2 *)
(* << Parameter setting processing >> /  / オブジェクトのインデックス番号とサブインデックス番号を指定します。 / Specify the index number and sub index number of the object. *)
_e1 := MOV(SM402, H1A00, MapTable[0].wIndex);
_e2 := MOV(_e1, 0, MapTable[0].wSubIndex);
MOV(_e2, 13, MapTable[13].wSubIndex);
MapTable[1].wIndex := MapTable[0].wIndex;
MapTable[2].wIndex := MapTable[0].wIndex;
MapTable[3].wIndex := MapTable[0].wIndex;
MOV(_e1, 1, MapTable[1].wSubIndex);
MOV(_e2, 14, MapTable[14].wSubIndex);
MapTable[4].wIndex := MapTable[0].wIndex;
MapTable[5].wIndex := MapTable[0].wIndex;
MapTable[6].wIndex := MapTable[0].wIndex;
MapTable[7].wIndex := MapTable[0].wIndex;
MOV(_e1, 2, MapTable[2].wSubIndex);
MOV(_e2, 15, MapTable[15].wSubIndex);
MapTable[8].wIndex := MapTable[0].wIndex;
MapTable[9].wIndex := MapTable[0].wIndex;
MapTable[10].wIndex := MapTable[0].wIndex;
MapTable[11].wIndex := MapTable[0].wIndex;
MOV(_e1, 3, MapTable[3].wSubIndex);
MOV(_e2, 16, MapTable[16].wSubIndex);
MapTable[12].wIndex := MapTable[0].wIndex;
MapTable[13].wIndex := MapTable[0].wIndex;
MapTable[14].wIndex := MapTable[0].wIndex;
MapTable[15].wIndex := MapTable[0].wIndex;
MOV(_e1, 4, MapTable[4].wSubIndex);
MOV(_e2, 17, MapTable[17].wSubIndex);
MapTable[16].wIndex := MapTable[0].wIndex;
MapTable[17].wIndex := MapTable[0].wIndex;
MapTable[18].wIndex := MapTable[0].wIndex;
MapTable[19].wIndex := MapTable[0].wIndex;
MOV(_e1, 5, MapTable[5].wSubIndex);
MOV(_e2, 18, MapTable[18].wSubIndex);
MapTable[20].wIndex := MapTable[0].wIndex;
MapTable[21].wIndex := MapTable[0].wIndex;
MapTable[22].wIndex := MapTable[0].wIndex;
MapTable[23].wIndex := MapTable[0].wIndex;
MOV(_e1, 6, MapTable[6].wSubIndex);
MOV(_e2, 19, MapTable[19].wSubIndex);
MapTable[24].wIndex := MapTable[0].wIndex;
MapTable[25].wIndex := MapTable[0].wIndex;
MOV(_e1, 7, MapTable[7].wSubIndex);
MOV(_e2, 20, MapTable[20].wSubIndex);
MOV(_e1, 8, MapTable[8].wSubIndex);
MOV(_e2, 21, MapTable[21].wSubIndex);
MOV(_e1, 9, MapTable[9].wSubIndex);
MOV(_e2, 22, MapTable[22].wSubIndex);
MOV(_e1, 10, MapTable[10].wSubIndex);
MOV(_e2, 23, MapTable[23].wSubIndex);
MOV(_e1, 11, MapTable[11].wSubIndex);
MOV(_e2, 24, MapTable[24].wSubIndex);
MOV(_e1, 12, MapTable[12].wSubIndex);
MOV(_e2, 25, MapTable[25].wSubIndex);
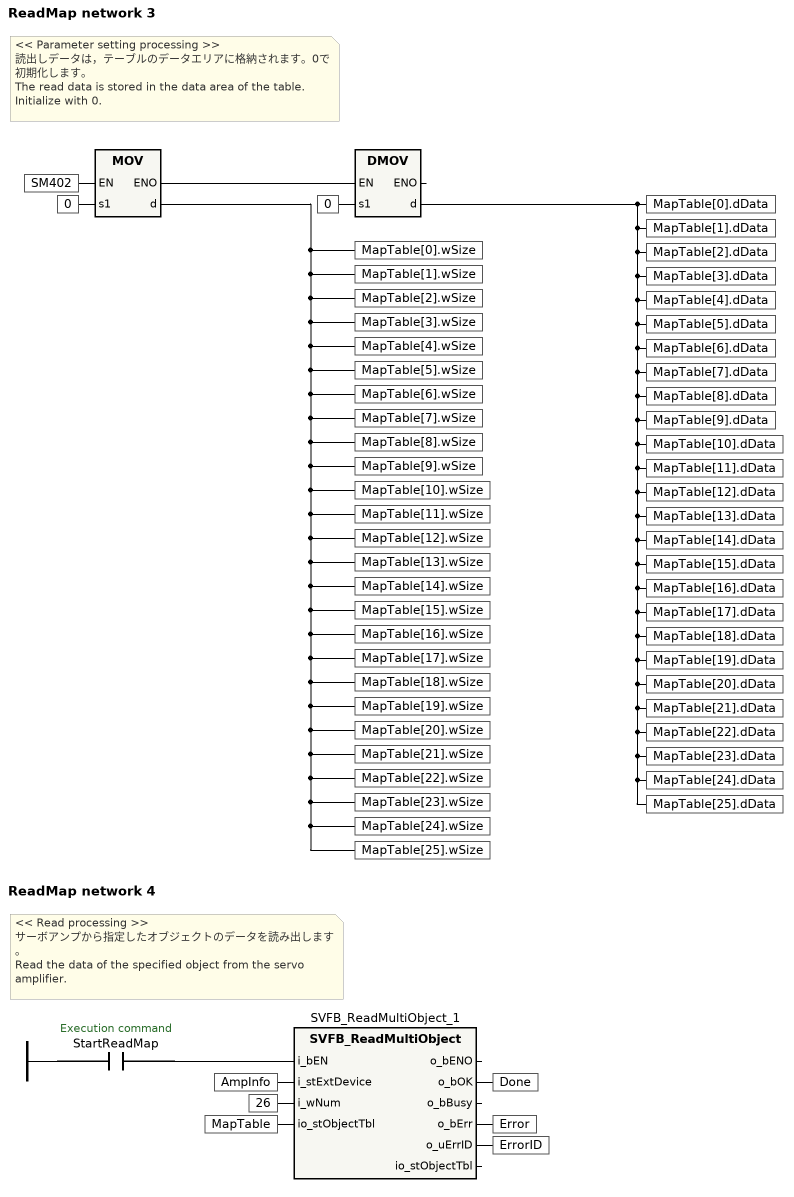
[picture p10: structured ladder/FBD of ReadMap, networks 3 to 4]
(* network 3 *)
(* << Parameter setting processing >> /  / 読出しデータは，テーブルのデータエリアに格納されます。0で初期化します。 / The read data is stored in the data area of the table. Initialize with 0. *)
_e1 := MOV(SM402, 0, MapTable[0].wSize);
DMOV(_e1, 0, MapTable[0].dData);
MapTable[1].wSize := MapTable[0].wSize;
MapTable[1].dData := MapTable[0].dData;
MapTable[2].wSize := MapTable[0].wSize;
MapTable[2].dData := MapTable[0].dData;
MapTable[3].wSize := MapTable[0].wSize;
MapTable[3].dData := MapTable[0].dData;
MapTable[4].wSize := MapTable[0].wSize;
MapTable[4].dData := MapTable[0].dData;
MapTable[5].wSize := MapTable[0].wSize;
MapTable[5].dData := MapTable[0].dData;
MapTable[6].wSize := MapTable[0].wSize;
MapTable[6].dData := MapTable[0].dData;
MapTable[7].wSize := MapTable[0].wSize;
MapTable[7].dData := MapTable[0].dData;
MapTable[8].wSize := MapTable[0].wSize;
MapTable[8].dData := MapTable[0].dData;
MapTable[9].wSize := MapTable[0].wSize;
MapTable[9].dData := MapTable[0].dData;
MapTable[10].wSize := MapTable[0].wSize;
MapTable[10].dData := MapTable[0].dData;
MapTable[11].wSize := MapTable[0].wSize;
MapTable[11].dData := MapTable[0].dData;
MapTable[12].wSize := MapTable[0].wSize;
MapTable[12].dData := MapTable[0].dData;
MapTable[13].wSize := MapTable[0].wSize;
MapTable[13].dData := MapTable[0].dData;
MapTable[14].wSize := MapTable[0].wSize;
MapTable[14].dData := MapTable[0].dData;
MapTable[15].wSize := MapTable[0].wSize;
MapTable[15].dData := MapTable[0].dData;
MapTable[16].wSize := MapTable[0].wSize;
MapTable[16].dData := MapTable[0].dData;
MapTable[17].wSize := MapTable[0].wSize;
MapTable[17].dData := MapTable[0].dData;
MapTable[18].wSize := MapTable[0].wSize;
MapTable[18].dData := MapTable[0].dData;
MapTable[19].wSize := MapTable[0].wSize;
MapTable[19].dData := MapTable[0].dData;
MapTable[20].wSize := MapTable[0].wSize;
MapTable[20].dData := MapTable[0].dData;
MapTable[21].wSize := MapTable[0].wSize;
MapTable[21].dData := MapTable[0].dData;
MapTable[22].wSize := MapTable[0].wSize;
MapTable[22].dData := MapTable[0].dData;
MapTable[23].wSize := MapTable[0].wSize;
MapTable[23].dData := MapTable[0].dData;
MapTable[24].wSize := MapTable[0].wSize;
MapTable[24].dData := MapTable[0].dData;
MapTable[25].wSize := MapTable[0].wSize;
MapTable[25].dData := MapTable[0].dData;
(* network 4 *)
(* << Read processing >> /  / サーボアンプから指定したオブジェクトのデータを読み出します。 / Read the data of the specified object from the servo amplifier. *)
SVFB_ReadMultiObject_1(i_bEN := StartReadMap, i_stExtDevice := AmpInfo, i_wNum := 26, io_stObjectTbl := MapTable, o_bOK => Done, o_bErr => Error, o_uErrID => ErrorID);
END_PROGRAM
